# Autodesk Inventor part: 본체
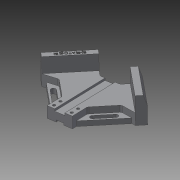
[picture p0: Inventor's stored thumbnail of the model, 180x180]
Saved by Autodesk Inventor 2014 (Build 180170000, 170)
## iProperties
Created: 2020-05
Part Number: 본체
Material: Generic
Document SubType Name: Modeling
Designer: kh
Density: 1 g/cm^3
Appearance: Default
Author: kh
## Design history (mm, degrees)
sketch "스케치6"
  geometry: L1 (0, 84.853)-(-84.853, 0); L2 (-84.853, 0)-(0, -84.853); L3 (0, -84.853)-(84.853, 0); L4 (84.853, 0)-(0, 84.853); 1 further point
  constraints: 8 end point, 3 horizontal alignment, 2 vertical alignment, 1 perpendicular
  dimensions: "d26" = 120 distance of L1.start L1.end; "d27" = 120 distance of L3.end L1.start; "d28" = 120 distance of L2.end L3.end
extrude "돌출4" new body sketch "스케치6" distance "d29" = 42; taper "d30" = 0 deg
sketch "스케치8"
  geometry: L1 (0, -84.853)-(84.853, 0) reference; L2 (-84.853, 0)-(0, -84.853) reference; L3 (-20, -64.853)-(20, -64.853); L4 (20, -64.853)-(0, -84.853); L5 (-20, -64.853)-(0, -84.853); 1 further point
  constraints: 6 end point, 2 collinear, 2 point on line, 1 horizontal
  dimensions: "d34" = 20 distance from line of L1.start L3
extrude "돌출5" cut sketch "스케치8" stored distance "d35" = 10; taper "d36" = 0 deg
sketch "스케치9"
  geometry: L1 (0, 84.853)-(-84.853, 0) reference; L2 (84.853, 0)-(0, 84.853) reference; L3 (-35.355, 49.497)-(-16.005, 30.147); L4 (-16.005, 30.147)-(16.005, 30.147); L5 (16.005, 30.147)-(35.355, 49.497); L6 (-20, -64.853)-(20, -64.853) reference; L7 (-35.355, 49.497)-(0, 84.853); L8 (0, 84.853)-(35.355, 49.497); 2 further points
  constraints: 10 end point, 2 collinear, 2 point on line, 1 horizontal, 1 midpoint, 1 parallel, 1 perpendicular, 1 vertical alignment
  dimensions: "d38" = 50 distance of L1.start L5.end; "d39" = 95 distance between parallel lines of L6 L4
extrude "돌출6" cut sketch "스케치9" stored distance "d40" = 10; taper "d41" = 0 deg
sketch "스케치10"
  geometry: L1 (-35.355, 49.497)-(-84.853, 0) reference; L2 (35.355, 49.497)-(16.005, 30.147) reference; L3 (16.005, 30.147)-(-16.005, 30.147) reference; L4 (-16.005, 30.147)-(-35.355, 49.497) reference; L5 (-35.355, 49.497)-(-84.853, 0) reference; L6 (-84.853, 0)-(-20, -64.853) reference; L7 (-20, -64.853)-(20, -64.853) reference; L8 (20, -64.853)-(84.853, 0) reference; L9 (84.853, 0)-(35.355, 49.497) reference; L10 (-74.246, -10.607)-(-24.749, 38.891); L11 (24.749, 38.891)-(74.246, -10.607); L12 (-24.749, 38.891)-(-16.005, 30.147); L13 (16.005, 30.147)-(24.749, 38.891); L14 (-16.005, 30.147)-(16.005, 30.147); L15 (-74.246, -10.607)-(-20, -64.853); L16 (-20, -64.853)-(20, -64.853); L17 (20, -64.853)-(74.246, -10.607); 1 further point
  constraints: 16 end point, 4 collinear, 4 point on line, 3 perpendicular, 1 parallel
  dimensions: "d42" = 15 distance between parallel lines of L1 L10; "d43" = 15 distance between parallel lines of L9 L11
extrude "돌출7" cut sketch "스케치10" distance "d44" = 24; taper "d45" = 0 deg
sketch "스케치11"
  geometry: L1 (16.005, 30.147)-(24.749, 38.891) reference; L2 (-16.005, 30.147)-(16.005, 30.147) reference; L3 (-24.749, 38.891)-(-16.005, 30.147) reference; L4 (-74.246, -10.607)-(-24.749, 38.891) reference; L5 (-20, -64.853)-(-74.246, -10.607) reference; L6 (20, -64.853)-(-20, -64.853) reference; L7 (74.246, -10.607)-(20, -64.853) reference; L8 (24.749, 38.891)-(74.246, -10.607) reference; L9 (-74.246, -10.607)-(-49.497, -7.071); L10 (-49.497, -7.071)-(-20, -36.569); L11 (-20, -36.569)-(-20, -64.853); L12 (20, -64.853)-(20, -36.569); L13 (-74.246, -10.607)-(-20, -64.853); L14 (20, -64.853)-(74.246, -10.607); L15 (-35.355, 49.497)-(-84.853, 0) reference; L16 (20, -36.569)-(49.497, -7.071); L17 (49.497, -7.071)-(74.246, -10.607); L18 (84.853, 0)-(35.355, 49.497) reference; L19 (-68.059, -9.723)-(-20, -57.782); L20 (20, -57.782)-(68.059, -9.723); 1 further point
  constraints: 20 end point, 5 parallel, 4 point on line, 1 perpendicular, 1 vertical
  dimensions: "d48" = 30 distance from line of L9.end L15; "d49" = 20 distance between parallel lines of L5 L10; "d51" = 20 distance between parallel lines of L7 L16; "d52" = 30 distance from line of L18 L16.end; "d55" = 5 distance between parallel lines of L19 L5; "d56" = 5 distance between parallel lines of L7 L20
  node "투영된 루프2"
extrude "돌출8" cut sketch "스케치11" distance "d53" = 10; taper "d54" = 0 deg
extrude "돌출9" cut sketch "스케치11" stored distance "d57" = 10; taper "d58" = 0 deg
sketch "스케치13"
  geometry: L1 (-68.059, -9.723)-(-20, -57.782) reference; L2 (-20, -36.569)-(-20, -57.782) reference; L3 (-49.497, -7.071)-(-20, -36.569) reference; L4 (-68.059, -9.723)-(-49.497, -7.071) reference; L5 (20, -57.782)-(68.059, -9.723) reference; L6 (49.497, -7.071)-(68.059, -9.723) reference; L7 (20, -36.569)-(49.497, -7.071) reference; L8 (20, -57.782)-(20, -36.569) reference; L9 (-49.497, -18.385)-(-29.698, -38.184); L10 (-52.326, -21.213)-(-32.527, -41.012); L11 (-26.87, -35.355)-(-46.669, -15.556); L12 (-35.355, 49.497)-(-84.853, 0) reference; L13 (-84.853, 0)-(-74.246, -10.607) reference; L14 (0, 0)-(0, -13.54); L15 (26.87, -35.355)-(46.669, -15.556); L16 (52.326, -21.213)-(32.527, -41.012); A1 r 4 centre (-49.497, -18.385) between (-46.669, -15.556) and (-52.326, -21.213); A2 r 4 centre (-29.698, -38.184) between (-32.527, -41.012) and (-26.87, -35.355); A3 r 4 centre (49.497, -18.385) between (52.326, -21.213) and (46.669, -15.556); A4 r 4 centre (29.698, -38.184) between (26.87, -35.355) and (32.527, -41.012); 1 further point
  constraints: 14 end point, 8 point on circle, 6 symmetric about line, 4 centre point, 4 tangent, 3 parallel, 1 midpoint, 2 other
  dimensions: "d59" = 38 distance from line of L12 L9.start; "d60" = 28 distance of L9.end L9.start; "d61" = 8 distance between parallel lines of L11 L10; "d63" = 12 distance from line of L13 point (-39.598, -28.284)
extrude "돌출10" cut sketch "스케치13" stored distance "d64" = 10; taper "d65" = 0 deg
sketch "스케치14"
  geometry: L1 (40, 0)-(0, 0) reference; L2 (12, 0)-(12, -3.5); L3 (12, -3.5)-(28, -3.5); L4 (28, -3.5)-(28, 0); L5 (40, -18)-(0, -18) reference; L6 (14, -15)-(26, -15); L7 (26, -15)-(26, -18); L8 (26, -18)-(14, -18); L9 (14, -18)-(14, -15); L10 (12, 0)-(28, 0); 5 further points
  constraints: 16 end point, 5 perpendicular, 4 midpoint, 3 point on line, 2 parallel, 1 coincident, 1 horizontal, 1 vertical alignment
  dimensions: "d66" = 16 distance of L2.end L3.end; "d67" = 3.5 distance of L3.end L4.end; "d68" = 12 distance of L6.start L6.end; "d69" = 3 distance of L6.end L7.end
extrude "돌출11" cut sketch "스케치14" stored distance "d70" = 10; taper "d71" = 0 deg
sketch "스케치16"
  geometry: L1 (-6, -30.147)-(-6, 64.853) reference; L2 (-6, 64.853)-(-20, 64.853) reference; L3 (-20, 64.853)-(-20, 57.782) reference; L4 (-20, 57.782)-(-68.059, 9.723) reference; L5 (-68.059, 9.723)-(-74.246, 10.607) reference; L6 (-84.853, 0)-(-74.246, 10.607) reference; L7 (-35.355, -49.497)-(-84.853, 0) reference; L8 (-35.355, -49.497)-(-16.005, -30.147) reference; L9 (-16.005, -30.147)-(-6, -30.147) reference; L10 (-26.87, 35.355)-(-46.669, 15.556) reference; L11 (-52.326, 21.213)-(-32.527, 41.012) reference; L12 (20, 57.782)-(20, 36.569) reference; L13 (6, 64.853)-(6, -30.147) reference; L14 (6, -30.147)-(16.005, -30.147) reference; L15 (16.005, -30.147)-(35.355, -49.497) reference; L16 (84.853, 0)-(35.355, -49.497) reference; L17 (74.246, 10.607)-(84.853, 0) reference; L18 (74.246, 10.607)-(68.059, 9.723) reference; L19 (68.059, 9.723)-(20, 57.782) reference; L20 (20, 57.782)-(20, 64.853) reference; L21 (20, 64.853)-(6, 64.853) reference; L22 (32.527, 41.012)-(52.326, 21.213) reference; L23 (46.669, 15.556)-(26.87, 35.355) reference; A1 r 4 centre (-29.698, 38.184) between (-26.87, 35.355) and (-32.527, 41.012) reference; A2 r 4 centre (-49.497, 18.385) between (-52.326, 21.213) and (-46.669, 15.556) reference; A3 r 4 centre (29.698, 38.184) between (32.527, 41.012) and (26.87, 35.355) reference; A4 r 4 centre (49.497, 18.385) between (46.669, 15.556) and (52.326, 21.213) reference; 5 further points
  constraints: 2 horizontal alignment, 2 vertical alignment
  dimensions: "d77" = 6 distance from line of L21 point (14, 58.853); "d78" = 12 distance of point (14, 58.853) point (14, 46.853); "d79" = 14 horizontal distance of point (0, 0) point (14, 58.853); "d80" = 28 distance of point (14, 58.853) point (-14, 58.853)
hole "구멍1" sketch "스케치16" at (-14, 58.853), (-14, 46.853), (14, 58.853), (14, 46.853) diameter "d81" = 4.5; stored, may be unused: countersink angle "d85" = 90 deg, drill point angle "d87" = 118 deg; dims "d82" = 6, "d83" = 8, "d84" = 10, "d86" = 8
chamfer "모따기1" distance "d88" = 5; stored, may be unused: second distance "d89" = 15, angle "d90" = 45 deg
chamfer "모따기2" distance "d91" = 5; stored, may be unused: second distance "d92" = 15, angle "d93" = 45 deg
fillet "모깎기1" dims "d94" = 5
sketch "스케치17"
  geometry: L1 (-81.317, -3.536)-(-31.82, 45.962) reference; L2 (-81.317, -3.536)-(-74.246, -10.607) reference; L3 (-74.246, -10.607)-(-24.749, 38.891) reference; L4 (-24.749, 38.891)-(-31.82, 45.962) reference; L5 (-37.614, 27.933)-(-63.288, 2.259); L6 (-63.288, 2.259)-(-68.452, 7.422); L7 (-68.452, 7.422)-(-42.778, 33.096); L8 (-42.778, 33.096)-(-37.614, 27.933); L9 (-63.288, 2.259)-(-42.778, 33.096); L10 (-68.452, 7.422)-(-37.614, 27.933); 4 further points
  constraints: 4 end point, 2 coincident, 1 midpoint, 2 other
  dimensions: "d95" = 5 distance from line of L3 point (-53.033, 17.678); "d96" = 35 distance from line of L4 point (-53.033, 17.678)
feature "엠보싱1" sketch "스케치17" dims "d26" = 120, "d38" = 50, "d39" = 95, "d97" = 0.5, "d98" = 0
fillet "모깎기2" dims "d99" = 5
node "솔리드2"
node "투영된 루프1"
node "투영된 루프3"
node "투영된 루프4"
node "투영된 루프7"
node "투영된 루프8"
node "투영된 루프9"
